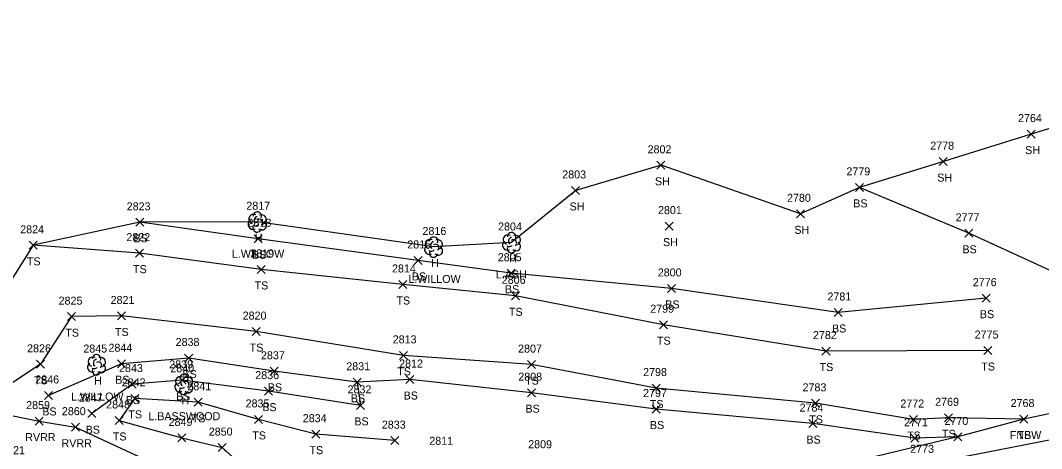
# Model space of a CAD drawing. Extents: x 1443590 to 1445966, y 578314 to 580556.
# Drawn here: x 1444295.6 to 1444550.7, y 579157.3 to 579264.3 of the extents above; entities that cross this region are included whole.
import ezdxf

# ---------------------------------------------------------------- set-up
doc = ezdxf.new("R2010")
doc.units = 0
for name, color, linetype in [('L_A', 7, 'Continuous'), ('L_C', 7, 'Continuous'), ('L_I', 7, 'Continuous'), ('L_TIC', 7, 'Continuous'), ('LABL', 7, 'Continuous'), ('LAWE', 7, 'Continuous'), ('LELB', 7, 'Continuous'), ('LFNC', 7, 'Continuous'), ('LSOGP', 7, 'Continuous'), ('LTD', 7, 'Continuous')]:
    doc.layers.add(name, color=color, linetype=linetype)

msp = doc.modelspace()

# ---------------------------------------------------------------- linework, layer by layer
at = {"layer": 'L_TIC'}
for points in [[(1444547.11, 579234.92), (1444549.11, 579236.92)], [(1444549.11, 579234.92), (1444547.11, 579236.92)], [(1444454.62, 579227.12), (1444456.62, 579229.12)], [(1444456.62, 579227.12), (1444454.62, 579229.12)], [(1444525.14, 579228.04), (1444527.14, 579230.04)], [(1444527.14, 579228.04), (1444525.14, 579230.04)], [(1444504.21, 579221.61), (1444506.21, 579223.61)], [(1444506.21, 579221.61), (1444504.21, 579223.61)], [(1444433.3, 579220.84), (1444435.3, 579222.84)], [(1444435.3, 579220.84), (1444433.3, 579222.84)], [(1444489.44, 579214.99), (1444491.44, 579216.99)], [(1444491.44, 579214.99), (1444489.44, 579216.99)], [(1444324.42, 579212.87), (1444326.42, 579214.87)], [(1444326.42, 579212.87), (1444324.42, 579214.87)], [(1444456.65, 579211.92), (1444458.65, 579213.92)], [(1444458.65, 579211.92), (1444456.65, 579213.92)], [(1444354.03, 579208.76), (1444356.03, 579210.76)], [(1444356.03, 579208.76), (1444354.03, 579210.76)], [(1444531.48, 579210.13), (1444533.48, 579212.13)], [(1444533.48, 579210.13), (1444531.48, 579212.13)], [(1444297.82, 579207.12), (1444299.82, 579209.12)], [(1444299.82, 579207.12), (1444297.82, 579209.12)], [(1444324.34, 579205.17), (1444326.34, 579207.17)], [(1444326.34, 579205.17), (1444324.34, 579207.17)], [(1444393.94, 579203.34), (1444395.94, 579205.34)], [(1444395.94, 579203.34), (1444393.94, 579205.34)], [(1444354.71, 579201.09), (1444356.71, 579203.09)], [(1444356.71, 579201.09), (1444354.71, 579203.09)], [(1444417.19, 579200.15), (1444419.19, 579202.15)], [(1444419.19, 579200.15), (1444417.19, 579202.15)], [(1444390.13, 579197.33), (1444392.13, 579199.33)], [(1444392.13, 579197.33), (1444390.13, 579199.33)], [(1444457.25, 579196.35), (1444459.25, 579198.35)], [(1444459.25, 579196.35), (1444457.25, 579198.35)], [(1444418.24, 579194.5), (1444420.24, 579196.5)], [(1444420.24, 579194.5), (1444418.24, 579196.5)], [(1444535.83, 579193.91), (1444537.83, 579195.91)], [(1444537.83, 579193.91), (1444535.83, 579195.91)], [(1444307.41, 579189.29), (1444309.41, 579191.29)], [(1444309.41, 579189.29), (1444307.41, 579191.29)], [(1444319.83, 579189.46), (1444321.83, 579191.46)], [(1444321.83, 579189.46), (1444319.83, 579191.46)], [(1444498.9, 579190.33), (1444500.9, 579192.33)], [(1444500.9, 579190.33), (1444498.9, 579192.33)], [(1444353.48, 579185.56), (1444355.48, 579187.56)], [(1444355.48, 579185.56), (1444353.48, 579187.56)], [(1444455.21, 579187.28), (1444457.21, 579189.28)], [(1444457.21, 579187.28), (1444455.21, 579189.28)], [(1444495.84, 579180.69), (1444497.84, 579182.69)], [(1444497.84, 579180.69), (1444495.84, 579182.69)], [(1444536.23, 579180.83), (1444538.23, 579182.83)], [(1444538.23, 579180.83), (1444536.23, 579182.83)], [(1444336.64, 579178.95), (1444338.64, 579180.95)], [(1444338.64, 579178.95), (1444336.64, 579180.95)], [(1444390.3, 579179.61), (1444392.3, 579181.61)], [(1444392.3, 579179.61), (1444390.3, 579181.61)], [(1444299.6, 579177.38), (1444301.6, 579179.38)], [(1444301.6, 579177.38), (1444299.6, 579179.38)], [(1444319.87, 579177.52), (1444321.87, 579179.52)], [(1444321.87, 579177.52), (1444319.87, 579179.52)], [(1444357.96, 579175.64), (1444359.96, 579177.64)], [(1444359.96, 579175.64), (1444357.96, 579177.64)], [(1444422.27, 579177.31), (1444424.27, 579179.31)], [(1444424.27, 579177.31), (1444422.27, 579179.31)], [(1444335.04, 579173.38), (1444337.04, 579175.38)], [(1444337.04, 579173.38), (1444335.04, 579175.38)], [(1444378.7, 579172.89), (1444380.7, 579174.89)], [(1444380.7, 579172.89), (1444378.7, 579174.89)], [(1444378.7, 579172.89), (1444380.7, 579174.89)], [(1444380.7, 579172.89), (1444378.7, 579174.89)], [(1444391.9, 579173.58), (1444393.9, 579175.58)], [(1444393.9, 579173.58), (1444391.9, 579175.58)], [(1444322.51, 579172.45), (1444324.51, 579174.45)], [(1444324.51, 579172.45), (1444322.51, 579174.45)], [(1444356.59, 579170.68), (1444358.59, 579172.68)], [(1444358.59, 579170.68), (1444356.59, 579172.68)], [(1444422.31, 579170.29), (1444424.31, 579172.29)], [(1444424.31, 579170.29), (1444422.31, 579172.29)], [(1444453.42, 579171.45), (1444455.42, 579173.45)], [(1444455.42, 579171.45), (1444453.42, 579173.45)], [(1444301.64, 579169.6), (1444303.64, 579171.6)], [(1444303.64, 579169.6), (1444301.64, 579171.6)], [(1444323.17, 579168.87), (1444325.17, 579170.87)], [(1444325.17, 579168.87), (1444323.17, 579170.87)], [(1444339, 579167.89), (1444341, 579169.89)], [(1444341, 579167.89), (1444339, 579169.89)], [(1444493.24, 579167.63), (1444495.24, 579169.63)], [(1444495.24, 579167.63), (1444493.24, 579169.63)], [(1444312.47, 579165.05), (1444314.47, 579167.05)], [(1444314.47, 579165.05), (1444312.47, 579167.05)], [(1444379.59, 579167.12), (1444381.59, 579169.12)], [(1444381.59, 579167.12), (1444379.59, 579169.12)], [(1444453.41, 579166.2), (1444455.41, 579168.2)], [(1444455.41, 579166.2), (1444453.41, 579168.2)], [(1444299.31, 579163.19), (1444301.31, 579165.19)], [(1444301.31, 579163.19), (1444299.31, 579165.19)], [(1444319.29, 579163.35), (1444321.29, 579165.35)], [(1444321.29, 579163.35), (1444319.29, 579165.35)], [(1444354.12, 579163.61), (1444356.12, 579165.61)], [(1444356.12, 579163.61), (1444354.12, 579165.61)], [(1444492.51, 579162.57), (1444494.51, 579164.57)], [(1444494.51, 579162.57), (1444492.51, 579164.57)], [(1444517.68, 579163.58), (1444519.68, 579165.58)], [(1444519.68, 579163.58), (1444517.68, 579165.58)], [(1444526.41, 579164.01), (1444528.41, 579166.01)], [(1444528.41, 579164.01), (1444526.41, 579166.01)], [(1444545.27, 579163.71), (1444547.27, 579165.71)], [(1444547.27, 579163.71), (1444545.27, 579165.71)], [(1444545.27, 579163.71), (1444547.27, 579165.71)], [(1444547.27, 579163.71), (1444545.27, 579165.71)], [(1444308.37, 579161.67), (1444310.37, 579163.67)], [(1444310.37, 579161.67), (1444308.37, 579163.67)], [(1444368.4, 579159.92), (1444370.4, 579161.92)], [(1444370.4, 579159.92), (1444368.4, 579161.92)], [(1444334.9, 579158.97), (1444336.9, 579160.97)], [(1444336.9, 579158.97), (1444334.9, 579160.97)], [(1444388.15, 579158.3), (1444390.15, 579160.3)], [(1444390.15, 579158.3), (1444388.15, 579160.3)], [(1444518.02, 579158.9), (1444520.02, 579160.9)], [(1444520.02, 579158.9), (1444518.02, 579160.9)], [(1444528.77, 579159.23), (1444530.77, 579161.23)], [(1444530.77, 579159.23), (1444528.77, 579161.23)], [(1444528.77, 579159.23), (1444530.77, 579161.23)], [(1444530.77, 579159.23), (1444528.77, 579161.23)], [(1444345, 579156.56), (1444347, 579158.56)], [(1444347, 579156.56), (1444345, 579158.56)]]:
    msp.add_lwpolyline(points, dxfattribs=at)
at = {"layer": 'LABL'}
msp.add_lwpolyline([(1444712.54, 579167.85), (1444697.6, 579169.93), (1444652.08, 579178.48), (1444624.95, 579180.17), (1444611.5, 579175.57), (1444588.82, 579169.39), (1444561.97, 579161.22), (1444521.13, 579153.26), (1444485.17, 579141.59), (1444461.96, 579127.68), (1444423.87, 579107.83), (1444406.2, 579097.14), (1444395.91, 579089.33), (1444383.1, 579088.69), (1444377.98, 579081.32), (1444375.45, 579066.09), (1444387.55, 579066.41), (1444398.68, 579076.41), (1444413.49, 579086.33)], dxfattribs=at)
at = {"layer": 'LAWE'}
msp.add_lwpolyline([(1444262.96, 579172.97), (1444274.11, 579169.09), (1444283.17, 579167.71), (1444300.31, 579164.19), (1444309.37, 579162.67), (1444332.16, 579152.06), (1444345.18, 579142.09), (1444354.88, 579132.23), (1444360.95, 579125.41), (1444366.81, 579116.47), (1444365.27, 579103.46), (1444363.21, 579091.32), (1444369.15, 579079.68), (1444366.13, 579066.94), (1444369.44, 579051.85), (1444379.35, 579035.17), (1444388.22, 579024.4)], dxfattribs=at)
at = {"layer": 'LELB'}
for points in [[(1444650.34, 579264.33), (1444627.7, 579251.43), (1444610.01, 579232.72), (1444599.82, 579220.48), (1444579.2, 579210.42), (1444554.69, 579201.02), (1444532.48, 579211.13), (1444505.21, 579222.61)], [(1444536.83, 579194.91), (1444499.9, 579191.33), (1444458.25, 579197.35), (1444418.19, 579201.15), (1444394.94, 579204.34), (1444355.03, 579209.76), (1444325.42, 579213.87)], [(1444537.23, 579181.83), (1444496.84, 579181.69), (1444456.21, 579188.28), (1444419.24, 579195.5), (1444391.13, 579198.33), (1444355.71, 579202.09), (1444325.34, 579206.17), (1444298.82, 579208.12)], [(1444546.27, 579164.71), (1444527.41, 579165.01), (1444518.68, 579164.58), (1444494.24, 579168.63), (1444454.42, 579172.45), (1444423.27, 579178.31), (1444391.3, 579180.61), (1444354.48, 579186.56), (1444320.83, 579190.46), (1444308.41, 579190.29), (1444300.6, 579178.38), (1444292.72, 579173.21), (1444274.67, 579178.92)], [(1444379.7, 579173.89), (1444358.96, 579176.64), (1444337.64, 579179.95), (1444320.87, 579178.52), (1444302.64, 579170.6)], [(1444529.77, 579160.23), (1444519.02, 579159.9), (1444493.51, 579163.57), (1444454.41, 579167.2), (1444423.31, 579171.29), (1444392.9, 579174.58), (1444379.7, 579173.89), (1444380.59, 579168.12), (1444357.59, 579171.68), (1444336.04, 579174.38), (1444323.51, 579173.45), (1444313.47, 579166.05)], [(1444389.15, 579159.3), (1444369.4, 579160.92), (1444355.12, 579164.61), (1444340, 579168.89), (1444324.17, 579169.87), (1444320.29, 579164.35), (1444335.9, 579159.97), (1444346, 579157.56), (1444357.85, 579146.86), (1444366.48, 579135.44), (1444376.19, 579122), (1444390.51, 579099.64)]]:
    msp.add_lwpolyline(points, dxfattribs=at)
at = {"layer": 'LFNC'}
msp.add_lwpolyline([(1444560.1, 579167.55), (1444546.27, 579164.71), (1444529.77, 579160.23), (1444480.82, 579148.51), (1444457.79, 579133.06), (1444422.53, 579110), (1444405.51, 579098.29), (1444395.54, 579091.93), (1444390.51, 579099.64), (1444385.34, 579099.67), (1444374.49, 579098.14), (1444368.47, 579095.23)], dxfattribs=at)
at = {"layer": 'LSOGP'}
msp.add_lwpolyline([(1444571.76, 579243.16), (1444548.12, 579235.92), (1444526.15, 579229.03), (1444505.22, 579222.61), (1444490.45, 579215.99), (1444455.64, 579228.12), (1444434.31, 579221.83), (1444418.27, 579208.83), (1444398.81, 579207.71), (1444354.75, 579214), (1444325.43, 579213.87), (1444298.83, 579208.12), (1444289.74, 579193.87)], dxfattribs=at)
at = {"layer": 'LTD'}
for p, q in [((1444354.74, 579214.01), (1444354.74, 579214.01)), ((1444354.74, 579214.01), (1444354.74, 579214.01)), ((1444418.26, 579208.83), (1444418.26, 579208.83)), ((1444418.26, 579208.83), (1444418.26, 579208.83)), ((1444398.8, 579207.71), (1444398.8, 579207.71)), ((1444398.8, 579207.71), (1444398.8, 579207.71)), ((1444314.59, 579178.32), (1444314.59, 579178.32)), ((1444314.59, 579178.32), (1444314.59, 579178.32)), ((1444336.41, 579173.41), (1444336.41, 579173.41)), ((1444336.41, 579173.41), (1444336.41, 579173.41))]:
    msp.add_line(p, q, dxfattribs=at)
for centre in [(1444354.78, 579215.44), (1444418.3, 579210.26), (1444398.84, 579209.15), (1444314.63, 579179.76), (1444336.46, 579174.85)]:
    msp.add_arc(centre, 1.05, 335.5272, 180.9563, dxfattribs=at)
for centre, major_axis, ratio, start_param, end_param in [((1444353.95, 579214.67), (1.21, -0.51), 0.895232, 1.570796, 4.712389), ((1444355.78, 579214.59), (-1.14, -0.48), 0.949671, 1.570796, 4.712389), ((1444353.65, 579213.3), (0.58, -1.04), 0.959034, 3.141593, 6.283185), ((1444354.28, 579213.26), (-0.625, -0.083), 0.423636, 0, 3.141593), ((1444354.53, 579214.47), (-0.208, -0.792), 0.645439, 3.141593, 6.283185), ((1444355.24, 579213.84), (-0.5, 0.667), 0.989748, 3.141593, 6.283185), ((1444355.74, 579213.17), (-1.09, 0.79), 0.841452, 1.570796, 4.712389), ((1444354.74, 579212.51), (0.26, 1.06), 0.942809, 1.570796, 4.712389), ((1444417.46, 579209.49), (1.21, -0.51), 0.895232, 1.570796, 4.712389), ((1444419.3, 579209.41), (-1.14, -0.48), 0.949671, 1.570796, 4.712389), ((1444397.71, 579207.01), (0.58, -1.04), 0.959034, 3.141593, 6.283185), ((1444398.01, 579208.38), (1.21, -0.51), 0.895232, 1.570796, 4.712389), ((1444398.59, 579208.17), (-0.208, -0.792), 0.645439, 3.141593, 6.283185), ((1444399.3, 579207.55), (-0.5, 0.667), 0.989748, 3.141593, 6.283185), ((1444399.8, 579206.88), (-1.09, 0.79), 0.841452, 1.570796, 4.712389), ((1444399.84, 579208.3), (-1.14, -0.48), 0.949671, 1.570796, 4.712389), ((1444417.17, 579208.12), (0.58, -1.04), 0.959034, 3.141593, 6.283185), ((1444417.8, 579208.08), (-0.625, -0.083), 0.423636, 0, 3.141593), ((1444418.05, 579209.29), (-0.208, -0.792), 0.645439, 3.141593, 6.283185), ((1444418.76, 579208.66), (-0.5, 0.667), 0.989748, 3.141593, 6.283185), ((1444419.26, 579207.99), (-1.09, 0.79), 0.841452, 1.570796, 4.712389), ((1444398.8, 579206.21), (0.26, 1.06), 0.942809, 1.570796, 4.712389), ((1444398.34, 579206.96), (-0.625, -0.083), 0.423636, 0, 3.141593), ((1444418.26, 579207.33), (0.26, 1.06), 0.942809, 1.570796, 4.712389), ((1444313.8, 579178.99), (1.21, -0.51), 0.895232, 1.570796, 4.712389), ((1444315.63, 579178.9), (-1.14, -0.48), 0.949671, 1.570796, 4.712389), ((1444313.5, 579177.61), (0.58, -1.04), 0.959034, 3.141593, 6.283185), ((1444314.13, 579177.57), (-0.625, -0.083), 0.423636, 0, 3.141593), ((1444314.38, 579178.78), (-0.208, -0.792), 0.645439, 3.141593, 6.283185), ((1444315.09, 579178.15), (-0.5, 0.667), 0.989748, 3.141593, 6.283185), ((1444315.59, 579177.49), (-1.09, 0.79), 0.841452, 1.570796, 4.712389), ((1444314.59, 579176.82), (0.26, 1.06), 0.942809, 1.570796, 4.712389), ((1444335.62, 579174.08), (1.21, -0.51), 0.895232, 1.570796, 4.712389), ((1444336.2, 579173.87), (-0.208, -0.792), 0.645439, 3.141593, 6.283185), ((1444337.45, 579174), (-1.14, -0.48), 0.949671, 1.570796, 4.712389), ((1444335.33, 579172.71), (0.58, -1.04), 0.959034, 3.141593, 6.283185), ((1444336.41, 579171.91), (0.26, 1.06), 0.942809, 1.570796, 4.712389), ((1444335.95, 579172.66), (-0.625, -0.083), 0.423636, 0, 3.141593), ((1444336.91, 579173.25), (-0.5, 0.667), 0.989748, 3.141593, 6.283185), ((1444337.41, 579172.58), (-1.09, 0.79), 0.841452, 1.570796, 4.712389)]:
    msp.add_ellipse(centre, major_axis=major_axis, ratio=ratio, start_param=start_param, end_param=end_param, dxfattribs=at)

# ---------------------------------------------------------------- texts
at = {"layer": 'L_A'}
for s, p in [('SH', (1444546.59, 579230.92)), ('SH', (1444524.63, 579224.04)), ('SH', (1444454.11, 579223.12)), ('SH', (1444432.79, 579216.84)), ('BS', (1444503.65, 579217.61)), ('SH', (1444488.93, 579210.99)), ('BS', (1444323.86, 579208.87)), ('H', (1444354.17, 579209.01)), ('SH', (1444456.13, 579207.92)), ('BS', (1444530.92, 579206.13)), ('BS', (1444353.47, 579204.76)), ('H', (1444417.69, 579203.83)), ('TS', (1444297.23, 579203.12)), ('TS', (1444323.75, 579201.17)), ('H', (1444398.23, 579202.71)), ('BS', (1444393.38, 579199.34)), ('TS', (1444354.12, 579197.09)), ('BS', (1444416.63, 579196.15)), ('TS', (1444389.54, 579193.33)), ('TS', (1444417.65, 579190.5)), ('BS', (1444456.69, 579192.35)), ('BS', (1444535.27, 579189.91)), ('TS', (1444319.24, 579185.46)), ('BS', (1444498.34, 579186.33)), ('TS', (1444306.82, 579185.29)), ('TS', (1444454.62, 579183.28)), ('TS', (1444352.89, 579181.56)), ('TS', (1444389.71, 579175.61)), ('TS', (1444495.25, 579176.69)), ('TS', (1444535.64, 579176.83)), ('TS', (1444299.01, 579173.38)), ('H', (1444314.02, 579173.32)), ('BS', (1444319.31, 579173.52)), ('BS', (1444336.08, 579174.95)), ('TS', (1444421.68, 579173.31)), ('BS', (1444357.4, 579171.64)), ('BS', (1444321.95, 579168.45)), ('BS', (1444334.48, 579169.38)), ('H', (1444335.84, 579168.41)), ('BS', (1444378.15, 579168.89)), ('BS', (1444378.15, 579168.89)), ('BS', (1444391.34, 579169.58)), ('TS', (1444452.83, 579167.45)), ('BS', (1444301.08, 579165.6)), ('BS', (1444356.03, 579166.68)), ('BS', (1444421.76, 579166.29)), ('TS', (1444322.58, 579164.87)), ('TS', (1444338.41, 579163.89)), ('BS', (1444379.03, 579163.12)), ('TS', (1444492.65, 579163.63)), ('BS', (1444311.91, 579161.05)), ('BS', (1444452.86, 579162.2)), ('TS', (1444525.82, 579160.01)), ('RVRR', (1444296.82, 579159.19)), ('RVRR', (1444305.88, 579157.67)), ('TS', (1444318.7, 579159.35)), ('TS', (1444353.53, 579159.61)), ('BS', (1444491.95, 579158.57)), ('TS', (1444517.09, 579159.58)), ('FNBW', (1444542.74, 579159.71)), ('TS', (1444544.68, 579159.71)), ('TS', (1444367.81, 579155.92))]:
    msp.add_text(s, height=2, dxfattribs=at).set_placement(p)
at = {"layer": 'L_C'}
for s, p in [('L.WILLOW', (1444348.44, 579205.01)), ('L.WILLOW', (1444392.5, 579198.71)), ('L.ASH', (1444414.38, 579199.83)), ('L.WILLOW', (1444308.29, 579169.32)), ('L.BASSWOOD', (1444327.57, 579164.41))]:
    msp.add_text(s, height=2, dxfattribs=at).set_placement(p)
at = {"layer": 'L_I'}
for s, p in [('2764', (1444544.8, 579238.92)), ('2778', (1444522.88, 579232.04)), ('2802', (1444452.28, 579231.12)), ('2803', (1444430.96, 579224.84)), ('2779', (1444501.94, 579225.61)), ('2780', (1444487.1, 579218.99)), ('2823', (1444322.16, 579216.87)), ('2817', (1444352.04, 579217.01)), ('2801', (1444454.87, 579215.92)), ('2777', (1444529.22, 579214.13)), ('2824', (1444295.56, 579211.12)), ('2818', (1444352.34, 579212.76)), ('2804', (1444414.92, 579211.83)), ('2822', (1444322.08, 579209.17)), ('2816', (1444396.05, 579210.71)), ('2815', (1444392.25, 579207.34)), ('2819', (1444353.01, 579205.09)), ('2805', (1444414.85, 579204.15)), ('2814', (1444388.43, 579201.33)), ('2806', (1444415.85, 579198.5)), ('2800', (1444454.82, 579200.35)), ('2776', (1444533.51, 579197.91)), ('2825', (1444305.15, 579193.29)), ('2821', (1444318.14, 579193.46)), ('2781', (1444497.2, 579194.33)), ('2799', (1444452.94, 579191.28)), ('2820', (1444351.13, 579189.56)), ('2838', (1444334.38, 579182.95)), ('2813', (1444388.61, 579183.61)), ('2782', (1444493.58, 579184.69)), ('2775', (1444533.97, 579184.83)), ('2826', (1444297.28, 579181.38)), ('2845', (1444311.33, 579181.32)), ('2844', (1444317.61, 579181.52)), ('2807', (1444419.93, 579181.31)), ('2837', (1444355.7, 579179.64)), ('2843', (1444320.25, 579176.45)), ('2839', (1444332.78, 579177.38)), ('2840', (1444333.06, 579176.41)), ('2831', (1444377.01, 579176.89)), ('2831', (1444377.01, 579176.89)), ('2812', (1444390.21, 579177.58)), ('2798', (1444451.16, 579175.45)), ('2846', (1444299.32, 579173.6)), ('2842', (1444320.91, 579172.87)), ('2836', (1444354.28, 579174.68)), ('2808', (1444419.98, 579174.29)), ('2841', (1444337.31, 579171.89)), ('2832', (1444377.33, 579171.12)), ('2797', (1444451.15, 579170.2)), ('2783', (1444490.98, 579171.63)), ('2847', (1444310.21, 579169.05)), ('2835', (1444351.86, 579167.61)), ('2772', (1444515.42, 579167.58)), ('2769', (1444524.1, 579168.01)), ('2768', (1444542.96, 579167.71)), ('2768', (1444542.96, 579167.71)), ('2859', (1444297.04, 579167.19)), ('2860', (1444305.97, 579165.67)), ('2848', (1444317.03, 579167.35)), ('2784', (1444490.25, 579166.57)), ('2849', (1444332.63, 579162.97)), ('2834', (1444366.14, 579163.92)), ('2771', (1444516.33, 579162.9)), ('2770', (1444526.43, 579163.23)), ('2770', (1444526.43, 579163.23)), ('2850', (1444342.66, 579160.56)), ('2833', (1444385.89, 579162.3)), ('2811', (1444397.74, 579158.26)), ('2809', (1444422.45, 579157.41)), ('3821', (1444290.81, 579155.92)), ('2773', (1444517.87, 579156.26))]:
    msp.add_text(s, height=2, dxfattribs=at).set_placement(p)

doc.saveas('drawing.dxf')
